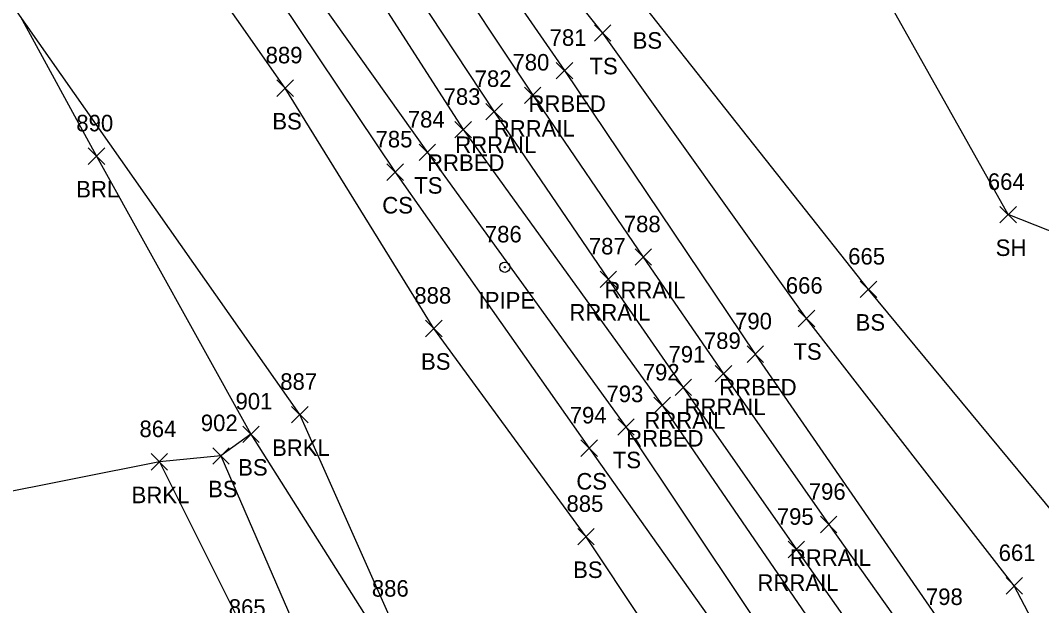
# Model space of a CAD drawing. Extents: x 1679360 to 1685861, y 903420 to 905946.
# Drawn here: x 1679676.5 to 1679800, y 904095.2 to 904166 of the extents above; entities that cross this region are included whole.
import ezdxf

# ---------------------------------------------------------------- set-up
doc = ezdxf.new("R2010")
doc.units = 0
for name, color, linetype in [('L_A', 7, 'Continuous'), ('L_I', 7, 'Continuous'), ('L_TIC', 7, 'Continuous'), ('LAWE', 7, 'Continuous'), ('LELB', 7, 'Continuous'), ('LSOGP', 7, 'Continuous'), ('M_A', 7, 'Continuous'), ('M_I', 7, 'Continuous'), ('MPIP', 7, 'Continuous'), ('R_A', 7, 'Continuous'), ('R_I', 7, 'Continuous'), ('R_TIC', 7, 'Continuous'), ('RR', 7, 'Continuous'), ('RRB', 7, 'Continuous')]:
    doc.layers.add(name, color=color, linetype=linetype)

msp = doc.modelspace()

# ---------------------------------------------------------------- linework, layer by layer
at = {"layer": 'L_TIC'}
for points in [[(1679745.93, 904163.44), (1679747.93, 904165.44)], [(1679747.93, 904163.44), (1679745.93, 904165.44)], [(1679707.52, 904156.77), (1679709.52, 904158.77)], [(1679709.52, 904156.77), (1679707.52, 904158.77)], [(1679724.72, 904149), (1679726.72, 904151)], [(1679726.72, 904149), (1679724.72, 904151)], [(1679684.7, 904148.54), (1679686.7, 904150.54)], [(1679686.7, 904148.54), (1679684.7, 904150.54)], [(1679720.82, 904146.6), (1679722.82, 904148.6)], [(1679722.82, 904146.6), (1679720.82, 904148.6)], [(1679794.98, 904141.46), (1679796.98, 904143.46)], [(1679796.98, 904141.46), (1679794.98, 904143.46)], [(1679778.08, 904132.42), (1679780.08, 904134.42)], [(1679780.08, 904132.42), (1679778.08, 904134.42)], [(1679770.59, 904128.9), (1679772.59, 904130.9)], [(1679772.59, 904128.9), (1679770.59, 904130.9)], [(1679725.51, 904127.69), (1679727.51, 904129.69)], [(1679727.51, 904127.69), (1679725.51, 904129.69)], [(1679709.28, 904117.26), (1679711.28, 904119.26)], [(1679711.28, 904117.26), (1679709.28, 904119.26)], [(1679748.74, 904115.77), (1679750.74, 904117.77)], [(1679750.74, 904115.77), (1679748.74, 904117.77)], [(1679703.38, 904114.88), (1679705.38, 904116.88)], [(1679705.38, 904114.88), (1679703.38, 904116.88)], [(1679744.3, 904113.19), (1679746.3, 904115.19)], [(1679746.3, 904113.19), (1679744.3, 904115.19)], [(1679699.75, 904112.26), (1679701.75, 904114.26)], [(1679701.75, 904112.26), (1679699.75, 904114.26)], [(1679692.3, 904111.54), (1679694.3, 904113.54)], [(1679694.3, 904111.54), (1679692.3, 904113.54)], [(1679743.91, 904102.49), (1679745.91, 904104.49)], [(1679745.91, 904102.49), (1679743.91, 904104.49)], [(1679795.72, 904096.55), (1679797.72, 904098.55)], [(1679797.72, 904096.55), (1679795.72, 904098.55)]]:
    msp.add_lwpolyline(points, dxfattribs=at)
at = {"layer": 'LAWE'}
for points in [[(1679721.41, 904093.23), (1679710.28, 904118.26), (1679642.61, 904214.69), (1679624.73, 904243.46), (1679599.05, 904283.15), (1679584.74, 904306.73)], [(1679693.3, 904112.54), (1679704.1, 904090.92), (1679709.49, 904071.53), (1679716.06, 904067.65)]]:
    msp.add_lwpolyline(points, dxfattribs=at)
at = {"layer": 'LELB'}
for points in [[(1679970.75, 904094.89), (1679956.12, 904082.48), (1679948.06, 904070.86), (1679945.89, 904046.82), (1679943.29, 904045.3), (1679931.1, 904045.75), (1679888.37, 904049.6), (1679852.38, 904057.08), (1679831.9, 904068.3), (1679818.58, 904068.02), (1679816.96, 904070.21), (1679822.07, 904077.46), (1679804.98, 904102.13), (1679779.08, 904133.42), (1679752.11, 904167.54), (1679728.27, 904203.83), (1679707.73, 904230.55), (1679684.13, 904262.03), (1679660.64, 904296.32), (1679637.49, 904331)], [(1679957.35, 904067.57), (1679950.7, 904052.36), (1679948.48, 904046.41), (1679946.09, 904041.57), (1679931.01, 904039.98), (1679888.72, 904042.9), (1679856.91, 904046.05), (1679830.24, 904050.06), (1679823.69, 904055.74), (1679818.78, 904061.51), (1679813.5, 904065.59), (1679796.72, 904097.55), (1679771.59, 904129.9), (1679746.93, 904164.44), (1679719.12, 904199.21), (1679701.21, 904226.94), (1679680.19, 904259.65), (1679656.34, 904293.81), (1679636.23, 904329.88)], [(1679619.82, 904321.42), (1679641.86, 904284.96), (1679662.72, 904251.2), (1679682.47, 904216.95), (1679699.46, 904186.97), (1679725.72, 904150), (1679749.74, 904116.77), (1679771.88, 904083.62), (1679794.81, 904052.66), (1679781.37, 904055.05), (1679771.63, 904053.63), (1679751.57, 904052.46), (1679718.64, 904054.59), (1679678.1, 904056.93), (1679638.82, 904059.88), (1679596.67, 904062.24), (1679555.45, 904065.45), (1679516.04, 904068.29), (1679469.12, 904071.92)], [(1679613.72, 904318.48), (1679636.27, 904281.99), (1679658.68, 904248.53), (1679679.07, 904215.01), (1679696.37, 904185.6), (1679721.82, 904147.6), (1679745.3, 904114.19), (1679768.75, 904081.07), (1679780.23, 904064.6), (1679777.26, 904058.93), (1679769.31, 904058.16), (1679752.16, 904056.65), (1679719.29, 904057.03), (1679678.41, 904059.75), (1679639.22, 904063.11), (1679596.82, 904065.62), (1679556, 904068.19), (1679515.9, 904070.74), (1679469.14, 904074.52)], [(1679469.87, 904080.86), (1679506.34, 904080.86), (1679543.9, 904078.61), (1679576.91, 904079.34), (1679615.93, 904077.92), (1679644, 904075.64), (1679674.59, 904072.69), (1679700.8, 904067.68), (1679715.25, 904064.96), (1679721.21, 904064.56), (1679726.22, 904064.25), (1679732.36, 904064.22), (1679738.12, 904066.05), (1679742.62, 904068.56), (1679755.32, 904068.1), (1679769.59, 904069.28), (1679758.63, 904082.85), (1679744.91, 904103.49), (1679726.51, 904128.69), (1679708.52, 904157.77), (1679684.84, 904191.6)], [(1679704.38, 904115.88), (1679726.77, 904080.38), (1679734.63, 904068.68), (1679730.36, 904066.6), (1679724.53, 904068.78), (1679720.61, 904066.87), (1679716.44, 904068.71)], [(1679700.75, 904113.26), (1679713.17, 904084.63), (1679716.44, 904068.71)]]:
    msp.add_lwpolyline(points, dxfattribs=at)
at = {"layer": 'LSOGP'}
for points in [[(1680125.11, 904075.81), (1680085.61, 904079.91), (1680037.11, 904084.02), (1680000.55, 904088.21), (1679990.54, 904090.48), (1679979.64, 904095.26), (1679970.75, 904094.89), (1679938.33, 904102.77), (1679898.72, 904102.15), (1679863.8, 904112.52), (1679834.59, 904127.23), (1679795.98, 904142.46), (1679772.54, 904184.21)], [(1679676.45, 904166.48), (1679685.7, 904149.54), (1679704.38, 904115.88), (1679700.75, 904113.26), (1679693.3, 904112.54), (1679672.44, 904108.38)]]:
    msp.add_lwpolyline(points, dxfattribs=at)
at = {"layer": 'MPIP'}
for radius in [0.625, 0.0833]:
    msp.add_circle((1679735.09, 904136.1), radius, dxfattribs=at)
at = {"layer": 'R_TIC'}
for points in [[(1679741.3, 904158.89), (1679743.3, 904160.89)], [(1679743.3, 904158.89), (1679741.3, 904160.89)], [(1679737.46, 904155.9), (1679739.46, 904157.9)], [(1679739.46, 904155.9), (1679737.46, 904157.9)], [(1679732.8, 904153.92), (1679734.8, 904155.92)], [(1679734.8, 904153.92), (1679732.8, 904155.92)], [(1679729.04, 904151.75), (1679731.04, 904153.75)], [(1679731.04, 904151.75), (1679729.04, 904153.75)], [(1679750.84, 904136.33), (1679752.84, 904138.33)], [(1679752.84, 904136.33), (1679750.84, 904138.33)], [(1679746.61, 904133.64), (1679748.61, 904135.64)], [(1679748.61, 904133.64), (1679746.61, 904135.64)], [(1679764.39, 904124.58), (1679766.39, 904126.58)], [(1679766.39, 904124.58), (1679764.39, 904126.58)], [(1679760.54, 904122.21), (1679762.54, 904124.21)], [(1679762.54, 904122.21), (1679760.54, 904124.21)], [(1679755.68, 904120.56), (1679757.68, 904122.56)], [(1679757.68, 904120.56), (1679755.68, 904122.56)], [(1679753.13, 904118.39), (1679755.13, 904120.39)], [(1679755.13, 904118.39), (1679753.13, 904120.39)], [(1679773.27, 904103.96), (1679775.27, 904105.96)], [(1679775.27, 904103.96), (1679773.27, 904105.96)], [(1679769.36, 904100.93), (1679771.36, 904102.93)], [(1679771.36, 904100.93), (1679769.36, 904102.93)]]:
    msp.add_lwpolyline(points, dxfattribs=at)
at = {"layer": 'RR'}
for points in [[(1679726.81, 904174.45), (1679738.46, 904156.9), (1679751.84, 904137.33), (1679761.54, 904123.21), (1679774.27, 904104.96), (1679784.87, 904090.08), (1679795.44, 904075.44), (1679806.42, 904060.67), (1679817.7, 904045.88), (1679831.29, 904028.45), (1679844.1, 904012.06)], [(1679722.86, 904171.49), (1679733.8, 904154.92), (1679747.61, 904134.64), (1679756.68, 904121.56), (1679770.36, 904101.93), (1679779.96, 904088.31), (1679791.05, 904073.02), (1679802.46, 904057.5), (1679811.73, 904045.41), (1679824.64, 904028.72), (1679837.34, 904012.39)]]:
    msp.add_lwpolyline(points, dxfattribs=at)
at = {"layer": 'RRB'}
for points in [[(1679633.2, 904329.89), (1679656.09, 904293.31), (1679676.78, 904259.06), (1679698.16, 904224.73), (1679716.55, 904197.16), (1679742.3, 904159.89), (1679765.39, 904125.58), (1679788.39, 904092.22), (1679811.33, 904062.99), (1679819.97, 904050.18)], [(1679622.51, 904322.69), (1679644.95, 904286.47), (1679665.07, 904252.34), (1679687.42, 904219.26), (1679705.66, 904190.77), (1679730.04, 904152.75), (1679754.13, 904119.39), (1679776.83, 904086.3), (1679798.02, 904055.8), (1679804.41, 904048.47)]]:
    msp.add_lwpolyline(points, dxfattribs=at)

# ---------------------------------------------------------------- texts
at = {"layer": 'L_A'}
for s, p in [('BS', (1679750.55, 904162.54)), ('TS', (1679745.33, 904159.44)), ('BS', (1679706.96, 904152.77)), ('BRL', (1679683.24, 904144.54)), ('TS', (1679724.13, 904145)), ('CS', (1679720.26, 904142.6)), ('SH', (1679794.47, 904137.46)), ('BS', (1679777.53, 904128.42)), ('TS', (1679770, 904124.9)), ('BS', (1679724.95, 904123.69)), ('BRKL', (1679706.93, 904113.26)), ('TS', (1679748.15, 904111.77)), ('BS', (1679702.83, 904110.88)), ('BS', (1679699.19, 904108.26)), ('CS', (1679743.74, 904109.19)), ('BRKL', (1679689.94, 904107.54)), ('BS', (1679743.35, 904098.49))]:
    msp.add_text(s, height=2, dxfattribs=at).set_placement(p)
at = {"layer": 'L_I'}
for s, p in [('889', (1679706.15, 904160.77)), ('890', (1679683.25, 904152.54)), ('784', (1679723.35, 904153)), ('785', (1679719.45, 904150.6)), ('664', (1679793.52, 904145.46)), ('665', (1679776.63, 904136.42)), ('666', (1679769.08, 904132.9)), ('888', (1679724.14, 904131.69)), ('887', (1679707.92, 904121.26)), ('793', (1679747.38, 904119.77)), ('901', (1679702.51, 904118.88)), ('794', (1679742.94, 904117.19)), ('864', (1679690.89, 904115.54)), ('902', (1679698.31, 904116.26)), ('885', (1679742.55, 904106.49)), ('661', (1679794.83, 904100.55)), ('886', (1679719, 904096.23)), ('886', (1679719, 904096.23)), ('865', (1679701.69, 904093.92))]:
    msp.add_text(s, height=2, dxfattribs=at).set_placement(p)
at = {"layer": 'M_A'}
msp.add_text('IPIPE', height=2, dxfattribs=at).set_placement((1679731.92, 904131.1))
at = {"layer": 'M_I'}
msp.add_text('786', height=2, dxfattribs=at).set_placement((1679732.67, 904139.1))
at = {"layer": 'R_A'}
for s, p in [('RRBED', (1679737.95, 904154.89)), ('RRRAIL', (1679733.75, 904151.9)), ('RRRAIL', (1679729.09, 904149.92)), ('RRBED', (1679725.68, 904147.75)), ('RRRAIL', (1679747.14, 904132.33)), ('RRRAIL', (1679742.9, 904129.64)), ('RRBED', (1679761.03, 904120.58)), ('RRRAIL', (1679756.83, 904118.21)), ('RRRAIL', (1679751.97, 904116.56)), ('RRBED', (1679749.77, 904114.39)), ('RRRAIL', (1679769.57, 904099.96)), ('RRRAIL', (1679765.65, 904096.93))]:
    msp.add_text(s, height=2, dxfattribs=at).set_placement(p)
at = {"layer": 'R_I'}
for s, p in [('781', (1679740.51, 904162.89)), ('780', (1679736.01, 904159.9)), ('782', (1679731.44, 904157.92)), ('783', (1679727.68, 904155.75)), ('788', (1679749.48, 904140.33)), ('787', (1679745.25, 904137.64)), ('790', (1679762.94, 904128.58)), ('789', (1679759.17, 904126.21)), ('791', (1679754.89, 904124.56)), ('792', (1679751.77, 904122.39)), ('796', (1679771.86, 904107.96)), ('795', (1679767.99, 904104.93)), ('798', (1679786.03, 904095.22))]:
    msp.add_text(s, height=2, dxfattribs=at).set_placement(p)

doc.saveas('drawing.dxf')
